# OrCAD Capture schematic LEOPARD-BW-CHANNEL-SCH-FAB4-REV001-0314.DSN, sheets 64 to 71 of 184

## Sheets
64 125_INTEL I210: size A2; title: INTEL I210
65 119_MB LED: size A3; title: MB LED
66 118_FAN - PWM: size A3; title: FAN -PWM
67 116_RESERVED PAGE: title: RESERVED PAGE
68 115_PECI: size A3; title: PECI
69 114_DEBUG PORT: size A3; title: DEBUG PORT
70 113_COM PORT: size A3; title: COM PORT
71 112_AST1250 ID SETTING: size A3; title: AST1250 ID SETTING

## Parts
sheet 112_AST1250 ID SETTING
R362  10KR2F-2-GP  [R402H16]
R366  10KR2F-2-GP  [R402H16]
R370  10KR2F-2-GP  [R402H16]
R378  10KR2F-2-GP  [R402H16]
R463  10KR2F-2-GP  [R402H16]
R465  10KR2F-2-GP  [R402H16]
R467  10KR2F-2-GP  [R402H16]
R468  10KR2F-2-GP  [R402H16]
R478  10KR2F-2-GP  [R402H16]
R484  10KR2F-2-GP  [R402H16]
R487  10KR2F-2-GP  [R402H16]
R494  10KR2F-2-GP  [R402H16]
R1132  10KR2F-2-GP  [R402H16]
R1134  10KR2F-2-GP  [R402H16]
R1136  10KR2F-2-GP  [R402H16]
R1138  10KR2F-2-GP  [R402H16]
R1140  10KR2F-2-GP  [R402H16]
R1141  10KR2F-2-GP  [R402H16]
R1157  10KR2F-2-GP  [R402H16]
R1158  10KR2F-2-GP  [R402H16]
R1159  10KR2F-2-GP  [R402H16]
R1160  10KR2F-2-GP  [R402H16]
R1161  10KR2F-2-GP  [R402H16]
R1162  10KR2F-2-GP  [R402H16]
R1163  10KR2F-2-GP  [R402H16]
R1164  10KR2F-2-GP  [R402H16]
R1165  10KR2F-2-GP  [R402H16]
R1166  10KR2F-2-GP  [R402H16]
R1167  10KR2F-2-GP  [R402H16]
R1168  10KR2F-2-GP  [R402H16]
R1169  10KR2F-2-GP  [R402H16]
R1170  10KR2F-2-GP  [R402H16]
sheet 113_COM PORT
C339  SCD1U16V2KX-3GP  [C402H22]
C688  SC180P50V2JN-1GP  [C402H22]
C689  SC180P50V2JN-1GP  [C402H22]
CN2  FCI-CON3-S1-GP  [68001-203HLF]
JP14  FCI-CON3-S1-GP  [68001-203HLF]
JP15  FCI-CON3-S1-GP  [68001-203HLF]
R262  0R2J-2-GP  [R402H16]
R263  0R2J-2-GP  [R402H16]
R372  1KR2F-3-GP  [R402H16]
R381  1KR2F-3-GP  [R402H16]
R1200  10KR2F-2-GP  [R402H16]
R1201  10KR2F-2-GP  [R402H16]
R1202  10KR2F-2-GP  [R402H16]
R1204  10KR2F-2-GP  [R402H16]
R1216  33R2F-3-GP  [R402H16]
R1218  33R2F-3-GP  [R402H16]
U46  SN74CB3Q3253PW-GP  [TSOIC16H48]
sheet 114_DEBUG PORT
C854  SCD1U16V2KX-3GP  [C402H22]
D4  BAT54C-12-GP  [SOT-23-9H44]
D27  1N4148WFL-GP  [SOD123AKH40]
D28  1N4148WFL-GP  [SOD123AKH40]
D29  1N4148WFL-GP  [SOD123AKH40]
DBG1  SMC-CONN14A-S5-GP  [ASP-165694-02]
JP5  FCI-CON3-S1-GP  [68001-203HLF]
Q4  LMBT3904LT1G-GP  [SOT23CBE2D4H44]
Q6  LMBT3904LT1G-GP  [SOT23CBE2D4H44]
Q7  2N7002-7F-GP  [SOT23DGS2D4H44]
Q23  2N7002-7F-GP  [SOT23DGS2D4H44]
R254  10KR2F-2-GP  [R402H16]
R271  0R2J-2-GP  [R402H16]
R280  0R2J-2-GP  [R402H16]
R374  15KR2F-GP  [R402H16]
R384  10KR2J-3-GP  [R402H16]
R385  10KR2J-3-GP  [R402H16]
R386  15KR2F-GP  [R402H16]
R387  10KR2J-3-GP  [R402H16]
R391  10KR2J-3-GP  [R402H16]
R407  0R2J-2-GP  [R402H16]
R409  1KR2J-1-GP  [R402H16]
R698  0R2J-2-GP  [R402H16]
R713  0R2J-2-GP  [R402H16]
R718  0R2J-2-GP  [R402H16]
R720  0R2J-2-GP  [R402H16]
R725  0R2J-2-GP  [R402H16]
sheet 115_PECI
R753  4K7R2F-GP  [R402H16]
R754  0R2J-2-GP  [R402H16]
R755  0R2J-2-GP  [R402H16]
R865  4K7R2F-GP  [R402H16]
sheet 118_FAN - PWM
C35  SCD1U50V3KX-GP  [C603H36]
C36  SCD1U50V3KX-GP  [C603H36]
C88  SCD1U16V2KX-3GP  [C402H22]
D12  MMSZ4701-V-GP  [SOD123AKH54]
D20  SDMK0340L-7-F-GP  [SOD323AKH42]
D21  SDMK0340L-7-F-GP  [SOD323AKH42]
D22  SDMK0340L-7-F-GP  [SOD323AKH42]
D23  SDMK0340L-7-F-GP  [SOD323AKH42]
D24  SDMK0340L-7-F-GP  [SOD323AKH42]
D25  SDMK0340L-7-F-GP  [SOD323AKH42]
F6  FUSE-15A65V-3-GP  [FUSE-6127H106]
FANCN1  LOTES-CON6-S1-GP  [YBA-WAF-016-K06]
FANCN2  LOTES-CON6-S1-GP  [YBA-WAF-016-K06]
R741  2K21R2F-GP  [R402H16]
R742  0R2J-2-GP  [R402H16]
R743  0R2J-2-GP  [R402H16]
R744  0R2J-2-GP  [R402H16]
R745  0R2J-2-GP  [R402H16]
R746  2K21R2F-GP  [R402H16]
R747  0R2J-2-GP  [R402H16]
R748  0R2J-2-GP  [R402H16]
R895  4K7R2F-GP  [R402H16]
R903  4K7R2F-GP  [R402H16]
U168  SOLVC2G07DBVR-GP  [SOT-6H58]
sheet 119_MB LED
BPLED1  LED-Y-70-GP  [LED3020AK-U2H44]
C1299  SCD1U16V2KX-3GP  [C402H22]
HDLED1  LED-G-147-GP  [LED3020AK-U2H44]
PWLED1  LED-B-77-GP-U3  [LED3020AK-U2H44]
Q20  2N7002-7F-GP  [SOT23DGS2D4H44]
R799  100R3F-1-GP  [R603H22]
R806  100R3F-1-GP  [R603H22]
R807  100R3F-1-GP  [R603H22]
R1155  100R3F-1-GP  [R603H22]
R1156  200R2F-L-GP  [R402H16]
R1868  0R2J-2-GP  [R402H16]
R1881  10KR2J-3-GP  [R402H16]
U42  74LVC1G86GW-GP  [SC70-5H44]
U48  NTJD4001NT1G-1-GP  [SOT-363H44]
ULED1  LED-G-107-GP-U  [LED11516AKH28]
ULED2  LED-G-107-GP-U  [LED11516AKH28]
sheet 125_INTEL I210
C317  SCD1U16V2KX-3GP  [C402H22]
C318  SCD1U16V2KX-3GP  [C402H22]
C319  SCD039U16V2KX-GP  [C402H22]
C323  SCD1U16V2KX-3GP  [C402H22]
C7280  SC12P50V2JN-3GP  [C402H24]
C7282  SC12P50V2JN-3GP  [C402H24]
LAN1  WGI210AT-2-GP  [QFN64G9-G3D6H40]  (sections A,B,C,D)
R343  0R3J-0-U-GP  [R603H22]
R344  0R3J-0-U-GP  [R603H22]
R383  0R3J-0-U-GP  [R603H22]
R894  10KR2F-2-GP  [R402H16]
R902  10KR2F-2-GP  [R402H16]
R904  10KR2F-2-GP  [R402H16]
R906  10KR2F-2-GP  [R402H16]
R907  100KR2J-1-GP  [R402H16]
R938  10KR2F-2-GP  [R402H16]
R941  10KR2F-2-GP  [R402H16]
R942  10KR2F-2-GP  [R402H16]
R949  3K3R2F-2-GP  [R402H16]
R950  3K3R2F-2-GP  [R402H16]
R951  3K3R2F-2-GP  [R402H16]
R953  3K3R2F-2-GP  [R402H16]
R978  3K3R2F-2-GP  [R402H16]
R982  3K3R2F-2-GP  [R402H16]
R1002  3K3R2F-2-GP  [R402H16]
R1004  3K3R2F-2-GP  [R402H16]
R1005  33K2R2F-GP  [R402H16]
R1008  33K2R2F-GP  [R402H16]
R1009  3K3R2F-2-GP  [R402H16]
R1010  33R2F-3-GP  [R402H16]
R1011  33R2F-3-GP  [R402H16]
R1012  33R2F-3-GP  [R402H16]
R1013  33R2F-3-GP  [R402H16]
R1014  33R2F-3-GP  [R402H16]
R1015  0R2J-2-GP  [R402H16]
R1232  10KR2F-2-GP  [R402H16]
R2126  0R2J-2-GP  [R402H16]
R2127  0R2J-2-GP  [R402H16]
R2129  4K99R2F-L-GP  [R402H16]
R2134  33R2F-3-GP  [R402H16]
R2157  10KR2F-2-GP  [R402H16]
R2158  10KR2F-2-GP  [R402H16]
R2159  10KR2F-2-GP  [R402H16]
R2165  0R2J-2-GP  [R402H16]
R2166  0R2J-2-GP  [R402H16]
TP471  TPAD28  [TPAD28]
TP472  TPAD28  [TPAD28]
TP474  TPAD28  [TPAD28]
TP475  TPAD28  [TPAD28]
TP476  TPAD28  [TPAD28]
TP477  TPAD28  [TPAD28]
TP478  TPAD28  [TPAD28]
TP479  TPAD28  [TPAD28]
TP480  TPAD28  [TPAD28]
U40  W25Q80DVSSIG-GP  [SOIC8-1H86]
X6  XTAL-25MHZ-96GP  [SMD49-4H56]

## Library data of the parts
R362 R378 R465 R478 R484 R487 R1134 R1161 = 10KR2F-2-GP: CHIP RES 10K F 1/16W 0402; Category: 240VA; GREENDFACTOR: R2_SA;R_SA;HF_SA;G_SA;; Level: SMD; Part Number: 64.10025.6DL; Part Type: SMD-RG; SPEC: http://wpqssvr.wistron.com.tw:7001/wpqs/servlet/COM.qpart.Attachment?PartNumber=64.10025.6DL
R366 R370 R463 R467 R468 R494 R1138 R1164 = 10KR2F-2-GP: CHIP RES 10K F 1/16W 0402; Category: 240VA; GREENDFACTOR: R2_SA;R_SA;HF_SA;G_SA;; Level: SMD; POP?: NOPOP; Part Number: 64.10025.6DL; Part Type: SMD-RG; SPEC: http://wpqssvr.wistron.com.tw:7001/wpqs/servlet/COM.qpart.Attachment?PartNumber=64.10025.6DL
R1132 R1136 R1162 R1163 = 10KR2F-2-GP: CHIP RES 10K F 1/16W 0402; Category: 240VA; GREENDFACTOR: R2_SA;R_SA;HF_SA;G_SA;; Level: SMD; POP?: NOPOP; Part Number: 64.10025.6DL; Part Type: SMD-RG; SPEC: http://wpqssvr.wistron.com.tw:7001/wpqs/servlet/COM.qpart.Attachment?PartNumber=64.10025.6DL; Status: POP
R1140 R1157 R1159 R1165 R1167 R1169 = 10KR2F-2-GP: CHIP RES 10K F 1/16W 0402; Category: 240VA; GREENDFACTOR: R2_SA;R_SA;HF_SA;G_SA;; Level: SMD; Part Number: 64.10025.6DL; Part Type: SMD-RG; SPEC: http://wpqssvr.wistron.com.tw:7001/wpqs/servlet/COM.qpart.Attachment?PartNumber=64.10025.6DL; Status: NOPOP
R1141 R1168 R1200-R1202 R1204 = 10KR2F-2-GP: CHIP RES 10K F 1/16W 0402; Category: 240VA; GREENDFACTOR: R2_SA;R_SA;HF_SA;G_SA;; Level: SMD; Part Number: 64.10025.6DL; Part Type: SMD-RG; SPEC: http://wpqssvr.wistron.com.tw:7001/wpqs/servlet/COM.qpart.Attachment?PartNumber=64.10025.6DL; Status: POP
R1158 R1160 R1166 R1170 = 10KR2F-2-GP: CHIP RES 10K F 1/16W 0402; Category: 240VA; GREENDFACTOR: R2_SA;R_SA;HF_SA;G_SA;; Level: SMD; POP?: NOPOP; Part Number: 64.10025.6DL; Part Type: SMD-RG; SPEC: http://wpqssvr.wistron.com.tw:7001/wpqs/servlet/COM.qpart.Attachment?PartNumber=64.10025.6DL; Status: NOPOP
C339 = SCD1U16V2KX-3GP: CHIP CAP C 0.1U 16V K0402 X7R; CATEGORIES: CAP_1.xV; GREENDFACTOR: R2_SA;HF_SA;G_SA;; MAIN_SOURCE: M; Part Number: 78.10421.2FL; Part Type: SMD-BCG; SPEC: http://wpqssvr.wistron.com.tw:7001/wpqs/servlet/COM.qpart.Attachment?PartNumber=78.10421.2FL
C688 C689 = SC180P50V2JN-1GP: CHIP CAP C 180P 50V J0402 NPO; GREENDFACTOR: R2_SA;HF_SA;G_SA;; Package Type: SMD-BCG; Part Number: 78.18134.1FL; SPEC: http://wpqssvr.wistron.com.tw:7001/wpqs/servlet/COM.qpart.Attachment?PartNumber=78.18134.1FL
CN2 JP14 JP15 = FCI-CON3-S1-GP: HEAD ML 1R3P ST 68001-203HLF; Category: PCH; GREENDFACTOR: R_SA;; Green Factor: R_SA;; Part Number: 21.61084.103; Part Type: CONN-G4; ROOM: IMMv2; S/D: DIP; SPEC: http://wpqssvr.wistron.com.tw:7001/wpqs/servlet/COM.qpart.Attachment?PartNumber=21.61084.103; Vender: FCI
R262 R263 = 0R2J-2-GP: CHIP RES 0 J 1/16W 0402; Category: LOM - i350; DESCRIPTIO: CHIP RES 0 J 1/16W 0402; GREENDFACTOR: R2_SA;HF_SA;G_SA;; Package Type: SMD-RG; Part Number: 63.R0034.1DL; Part Type: SMD-RG; SPEC: http://wpqssvr.wistron.com.tw:7001/wpqs/servlet/COM.qpart.Attachment?PartNumber=63.R0034.1DL; VENDORPARTNUMBER: RM04JTN0/RTT02000JTH/RR0510X-000-XN/RC0402JR-070RL/WR04X000 PTL
R372 R381 = 1KR2F-3-GP: CHIP RES 1K F 1/16W 0402; GREENDFACTOR: R2_SA;HF_SA;G_SA;; Package Type: SMD-RG; Part Number: 64.10015.6DL; SPEC: http://wpqssvr.wistron.com.tw:7001/wpqs/servlet/COM.qpart.Attachment?PartNumber=64.10015.6DL
R1216 R1218 = 33R2F-3-GP: CHIP RES 33 F 1/16W 0402(ROHS); Category: PILOT3; GREENDFACTOR: R2_SA;HF_SA;G_SA;; Package Type: SMD-RG; Part Number: 64.33R05.6DL; Quotation: 12_14; Type: SMD
U46 = SN74CB3Q3253PW-GP: IC BUS SN74CB3Q3253PW TSSOP16P; GREENDFACTOR: R2_SA;; Part Number: 73.03253.A0B; Part Type: DISCRET-G4; SPEC: http://wpqssvr.wistron.com.tw:7001/wpqs/servlet/COM.qpart.Attachment?PartNumber=73.03253.A0B
C854 = SCD1U16V2KX-3GP: CHIP CAP C 0.1U 16V K0402 X7R; Belong: POP; CATEGORIES: CAP_1.xV; Category: USB SW / Debug; GREENDFACTOR: R2_SA;HF_SA;G_SA;; MAIN_SOURCE: M; Part Number: 78.10421.2FL; Part Type: SMD-BCG; SPEC: http://wpqssvr.wistron.com.tw:7001/wpqs/servlet/COM.qpart.Attachment?PartNumber=78.10421.2FL
D4 = BAT54C-12-GP: IC DIODE S.B BAT54C SOT-23; GREENDFACTOR: R2_SA;HF_SA;G_SA;; Package Type: DISCRET-G9; Part Number: 75.00054.A7D; SPEC: http://wpqssvr.wistron.com.tw:7001/wpqs/servlet/COM.qpart.Attachment?PartNumber=75.00054.A7D
D27-D29 = 1N4148WFL-GP: DIODE SW 1N4148WFL SOD-123; Belong: POP; Category: I/O CONN; GREENDFACTOR: R_SA;HF_SA;; Part Number: 83.04148.F1H; Part Type: DISCRET-G5; SPEC: http://wpqssvr.wistron.com.tw:7001/wpqs/servlet/COM.qpart.Attachment?PartNumber=83.04148.F1H
DBG1 = SMC-CONN14A-S5-GP: CONN CTR 14P ASP-165694-02; GREENDFACTOR: R2_C;HF_C;; Part Number: 020.80491.0014; Part Type: CONN-G4; SPEC: http://wpqssvr.wistron.com.tw:7001/wpqs/servlet/COM.qpart.Attachment?PartNumber=020.80491.0014
JP5 = FCI-CON3-S1-GP: HEAD ML 1R3P ST 68001-203HLF; GREENDFACTOR: R2_SA;; Part Number: 21.61084.103; Part Type: CONN-G4; SPEC: http://wpqssvr.wistron.com.tw:7001/wpqs/servlet/COM.qpart.Attachment?PartNumber=21.61084.103
Q4 Q6 = LMBT3904LT1G-GP: XTOR LMBT3904LT1G NPN SOT-23; GREENDFACTOR: R2_SA;HF_SA;G_SA;; Part Number: 84.T3904.H11; Part Type: DISCRET-G6; SPEC: http://wpqssvr.wistron.com.tw:7001/wpqs/servlet/COM.qpart.Attachment?PartNumber=84.T3904.H11
Q7 Q20 Q23 = 2N7002-7F-GP: FET MOS 2N7002-7-F NC SOT-23; GREENDFACTOR: R2_SA;HF_SA;G_SA;; Part Number: 84.27002.N31; Part Type: DISCRET-G; SPEC: http://wpqssvr.wistron.com.tw:7001/wpqs/servlet/COM.qpart.Attachment?PartNumber=84.27002.N31
R254 = 10KR2F-2-GP: CHIP RES 10K F 1/16W 0402; Category: PCH; DESCRIPTIO: CHIP RES 10K F 1/16W 0402; GREENDFACTOR: R2_SA;HF_SA;G_SA;; Package Type: SMD-RG; Part Number: 64.10025.6DL; Part Type: SMD-RG; SPEC: http://wpqssvr.wistron.com.tw:7001/wpqs/servlet/COM.qpart.Attachment?PartNumber=64.10025.6DL; VENDORPARTNUMBER: RM04FTN1002 / RTT021002FTH / RR0510S-103-FN / RC0402FR-0710KL/WR04X1002FTL
R271 R280 R407 R698 R713 R718 R720 R725 R742-R745 R747 R748 R755 R1868 = 0R2J-2-GP: CHIP RES 0 J 1/16W 0402; Category: BMC; DESCRIPTIO: CHIP RES 0 J 1/16W 0402; GREENDFACTOR: R2_SA;HF_SA;G_SA;; Package Type: SMD-RG; Part Number: 63.R0034.1DL; Part Type: SMD-RG; SPEC: http://wpqssvr.wistron.com.tw:7001/wpqs/servlet/COM.qpart.Attachment?PartNumber=63.R0034.1DL; VENDORPARTNUMBER: RM04JTN0/RTT02000JTH/RR0510X-000-XN/RC0402JR-070RL/WR04X000 PTL
R374 R386 = 15KR2F-GP: CHIP RES 15K F 1/16W 0402; GREENDFACTOR: R2_SA;HF_SA;G_SA;; Part Number: 64.15025.6DL; Part Type: RCL_GP; SPEC: http://wpqssvr.wistron.com.tw:7001/wpqs/servlet/COM.qpart.Attachment?PartNumber=64.15025.6DL
R384 R385 R387 R391 R1881 = 10KR2J-3-GP: CHIP RES 10K J 1/16W 0402; Category: PWRI/O CONN; GREENDFACTOR: R2_SA;HF_SA;G_SA;; Module: Internal Connector; Package Type: SMD-RG; Part Number: 63.10334.1DL; SPEC: http://wpqssvr.wistron.com.tw:7001/wpqs/servlet/COM.qpart.Attachment?PartNumber=63.10334.1DL
R409 = 1KR2J-1-GP: CHIP RES 1K J 1/16W 0402; GREENDFACTOR: R2_SA;HF_SA;G_SA;; Part Number: 63.10234.1DL; Part Type: SMD-RG; SPEC: http://wpqssvr.wistron.com.tw:7001/wpqs/servlet/COM.qpart.Attachment?PartNumber=63.10234.1DL
R753 = 4K7R2F-GP: CHIP RES 4.7K F 1/16W 0402; Category: BMC; DESCRIPTIO: CHIP RES 4.7K F 1/16W 0402; GREENDFACTOR: R2_SA;HF_SA;G_SA;; POP?: NOPOP; Package Type: RCL_GP; Part Number: 64.47015.6DL; Part Type: RCL_GP; SPEC: http://wpqssvr.wistron.com.tw:7001/wpqs/servlet/COM.qpart.Attachment?PartNumber=64.47015.6DL; VENDORPARTNUMBER: RM04FTN4701/RTT024701FTH/RR0510S-472-FN/RC0402FR-074K7L/WR04X4701FTL
R754 = 0R2J-2-GP: CHIP RES 0 J 1/16W 0402; Category: BMC; DESCRIPTIO: CHIP RES 0 J 1/16W 0402; GREENDFACTOR: R2_SA;HF_SA;G_SA;; POP?: NOPOP; Package Type: SMD-RG; Part Number: 63.R0034.1DL; Part Type: SMD-RG; SPEC: http://wpqssvr.wistron.com.tw:7001/wpqs/servlet/COM.qpart.Attachment?PartNumber=63.R0034.1DL; VENDORPARTNUMBER: RM04JTN0/RTT02000JTH/RR0510X-000-XN/RC0402JR-070RL/WR04X000 PTL
R865 = 4K7R2F-GP: CHIP RES 4.7K F 1/16W 0402; Category: BMC; DESCRIPTIO: CHIP RES 4.7K F 1/16W 0402; GREENDFACTOR: R2_SA;HF_SA;G_SA;; Package Type: RCL_GP; Part Number: 64.47015.6DL; Part Type: RCL_GP; SPEC: http://wpqssvr.wistron.com.tw:7001/wpqs/servlet/COM.qpart.Attachment?PartNumber=64.47015.6DL; VENDORPARTNUMBER: RM04FTN4701/RTT024701FTH/RR0510S-472-FN/RC0402FR-074K7L/WR04X4701FTL
C35 C36 = SCD1U50V3KX-GP: CHIP CAP C 0.1U 50V K0603 X7R; CATEGORIES: CAP_1.xV; GREENDFACTOR: R2_SA;R_SA;HF_SA;G_SA;; MAIN_SOURCE: M; Package Type: RCL_GP; Part Number: 78.10424.2BL; SPEC: http://wpqssvr.wistron.com.tw:7001/wpqs/servlet/COM.qpart.Attachment?PartNumber=78.10424.2BL
C88 = SCD1U16V2KX-3GP: CHIP CAP C 0.1U 16V K0402 X7R; Category: CLK GEN; GREENDFACTOR: R_SA;HF_SA;G_SA;; Part Number: 78.10421.2FL; Quotation: 13_8; Type: SMD
D12 = MMSZ4701-V-GP: DIODE ZENER MMSZ4701-V SOD123; GREENDFACTOR: R_C;; POP?: NOPOP; Package Type: DISCRET-G; Part Number: 83.14R03.03H; SPEC: http://wpqssvr.wistron.com.tw:7001/wpqs/servlet/COM.qpart.Attachment?PartNumber=83.14R03.03H
D20-D23 = SDMK0340L-7-F-GP: DIODE SDMK0340L-7-F SOD-323; GREENDFACTOR: R2_SA;HF_SA;; Part Number: 83.R3004.A8F; Part Type: DISCRET-G; SPEC: http://wpqssvr.wistron.com.tw:7001/wpqs/servlet/COM.qpart.Attachment?PartNumber=83.R3004.A8F
D24 D25 = SDMK0340L-7-F-GP: DIODE SDMK0340L-7-F SOD-323; GREENDFACTOR: R2_SA;HF_SA;G_SA;; POP?: NOPOP; Part Number: 83.R3004.A8F; Part Type: DISCRET-G; SPEC: http://wpqssvr.wistron.com.tw:7001/wpqs/servlet/COM.qpart.Attachment?PartNumber=83.R3004.A8F
F6 = FUSE-15A65V-3-GP: CHIP FUSE 15A 65V R451015; GREENDFACTOR: R_SA;; Part Number: 69.41502.011; Part Type: DISCRET-G6; SPEC: http://wpqssvr.wistron.com.tw:7001/wpqs/servlet/COM.qpart.Attachment?PartNumber=69.41502.011
FANCN1 FANCN2 = LOTES-CON6-S1-GP: HEAD ML 1R6P ST YBA-WAF-016-K06; GREENDFACTOR: R2_C;; Part Number: 21.61901.106; Part Type: CONN-G5; SPEC: http://wpqssvr.wistron.com.tw:7001/wpqs/servlet/COM.qpart.Attachment?PartNumber=21.61901.106
R741 R746 = 2K21R2F-GP: CHIP RES 2.21K F 1/16W 0402; Category: HOTPLUG_CONTROL; GREENDFACTOR: R2_SA;HF_SA;G_SA;; POP?: NOPOP; Package Type: RCL_GP; Part Number: 64.22115.6DL; Part Type: RCL_GP; SPEC: http://wpqssvr.wistron.com.tw:7001/wpqs/servlet/COM.qpart.Attachment?PartNumber=64.22115.6DL
R895 R903 = 4K7R2F-GP: CHIP RES 4.7K F 1/16W 0402; Category: internal conn; DESCRIPTIO: CHIP RES 4.7K F 1/16W 0402; GREENDFACTOR: R2_SA;HF_SA;G_SA;; POP?: NOPOP; Package Type: RCL_GP; Part Number: 64.47015.6DL; Part Type: RCL_GP; SPEC: http://wpqssvr.wistron.com.tw:7001/wpqs/servlet/COM.qpart.Attachment?PartNumber=64.47015.6DL; VENDORPARTNUMBER: RM04FTN4701/RTT024701FTH/RR0510S-472-FN/RC0402FR-074K7L/WR04X4701FTL
U168 = SOLVC2G07DBVR-GP: IC BUF/DRV SN74LVC2G07DBVR SOT23-6; GREENDFACTOR: R2_SA;HF_SA;; Part Number: 73.2G07D.020; Part Type: TTL-G6; SPEC: http://wpqssvr.wistron.com.tw:7001/wpqs/servlet/COM.qpart.Attachment?PartNumber=73.2G07D.020
BPLED1 = LED-Y-70-GP: LED YEL 12-21UYC/S530-A3/TR8; Category: LED_WOL; GREENDFACTOR: R_SA;; POP?: POP; Part Number: 83.01221.Q70; Part Type: DISCRET-G5; SPEC: http://wpqssvr.wistron.com.tw:7001/wpqs/servlet/COM.qpart.Attachment?PartNumber=83.01221.Q70
C1299 = SCD1U16V2KX-3GP: CHIP CAP C 0.1U 16V K0402 X7R; Belong: POP; CATEGORIES: CAP_1.xV; Category: UID LED; GREENDFACTOR: R2_SA;HF_SA;G_SA;; MAIN_SOURCE: M; Part Number: 78.10421.2FL; Part Type: SMD-BCG; SPEC: http://wpqssvr.wistron.com.tw:7001/wpqs/servlet/COM.qpart.Attachment?PartNumber=78.10421.2FL
HDLED1 = LED-G-147-GP: LED G 12-21SYGC/S530-E4/TR8; Category: LED_WOL; GREENDFACTOR: R2_SA;; POP?: POP; Part Number: 83.01221.N70; Part Type: DISCRET-G2; SPEC: http://wpqssvr.wistron.com.tw:7001/wpqs/servlet/COM.qpart.Attachment?PartNumber=83.01221.N70
PWLED1 = LED-B-77-GP-U3: LED BLUE 12-21/BHC-YLMRY-2C; Category: UID LED; GREENDFACTOR: R2_SA;HF_SA;; POP?: POP; Package Type: DISCRET-G6; Part Number: 83.01221.I70; SPEC: http://wpqssvr.wistron.com.tw:7001/wpqs/servlet/COM.qpart.Attachment?PartNumber=83.01221.I70
R799 R806 R807 R1155 = 100R3F-1-GP: CHIP RES 100 F 1/10W 0603(ROHS; Category: LED_WOL; GREENDFACTOR: R2_SA;HF_SA;G_SA;; Package Type: SMD-RG6; Part Number: 64.10005.55L; SPEC: http://wpqssvr.wistron.com.tw:7001/wpqs/servlet/COM.qpart.Attachment?PartNumber=64.10005.55L
R1156 = 200R2F-L-GP: CHIP RES 200 F 1/16W 0402; Belong: POP; Category: UID LED; GREENDFACTOR: R2_SA;HF_SA;G_SA;; Part Number: 64.20005.6DL; Part Type: SMD-RG; SPEC: http://wpqssvr.wistron.com.tw:7001/wpqs/servlet/COM.qpart.Attachment?PartNumber=64.20005.6DL
U42 = 74LVC1G86GW-GP: IC CMOS 74LVC1G86GW SC-88A; GREENDFACTOR: R2_SA;HF_SA;; Part Number: 73.01G86.AHH; Part Type: DISCRET-G; SPEC: http://wpqssvr.wistron.com.tw:7001/wpqs/servlet/COM.qpart.Attachment?PartNumber=73.01G86.AHH
U48 = NTJD4001NT1G-1-GP: IC MOSFET NTJD4001NT1G NC SOT-363 6P; GREENDFACTOR: R2_SA;; Part Number: 75.04001.07C; Part Type: DISCRET-G5; SPEC: http://wpqssvr.wistron.com.tw:7001/wpqs/servlet/COM.qpart.Attachment?PartNumber=75.04001.07C
ULED1 ULED2 = LED-G-107-GP-U: LED GREEN LTST-S270KGKT SMD; GREENDFACTOR: R2_SA;HF_SA;G_SA;; Part Number: 83.00270.B70; Part Type: DISCRET-G; SPEC: http://wpqssvr.wistron.com.tw:7001/wpqs/servlet/COM.qpart.Attachment?PartNumber=83.00270.B70
C317 C318 C323 = SCD1U16V2KX-3GP: CHIP CAP C 0.1U 16V K0402 X7R; Category: CLK GEN; GREENDFACTOR: R_SA;HF_SA;G_SA;; POP?: NOPOP; Part Number: 78.10421.2FL; Quotation: 13_8; Type: SMD
C319 = SCD039U16V2KX-GP: CHIP CAP C 0.039U 16V K0402 X7; GREENDFACTOR: R2_SA;HF_SA;G_SA;; POP?: NOPOP; Package Type: SMD-BCG3; Part Number: 78.39321.2FL; SPEC: http://wpqssvr.wistron.com.tw:7001/wpqs/servlet/COM.qpart.Attachment?PartNumber=78.39321.2FL
C7280 C7282 = SC12P50V2JN-3GP: CHIP CAP C 12P 50V J0402 NPO; CATEGORIES: CAP_Small; Category: Clock; GREENDFACTOR: R2_SA;HF_SA;G_SA;; MAIN_SOURCE: M; POP?: NOPOP; Package Type: SMD-BCG; Part Number: 78.12034.1FL; Part Type: SMD-BCG; SPEC: http://wpqssvr.wistron.com.tw:7001/wpqs/servlet/COM.qpart.Attachment?PartNumber=78.12034.1FL; VENDORPARTNUMBER: 04025A120JAT2A/GRM1555C1H120JZ01D/223886915129/UMK105CH120JW-F/C1005C0G1H120J/C1005NP0120JGT/GRM1555C1H120JA01D/0402N120J500
LAN1 = WGI210AT-2-GP: IC WGI210AT SLJXR MM#925132 A2 QFN 64P; GREENDFACTOR: R2_SA;; POP?: NOPOP; Part Number: 071.210AT.0003; Part Type: ASIC2-GB1; SPEC: http://wpqssvr.wistron.com.tw:7001/wpqs/servlet/COM.qpart.Attachment?PartNumber=071.210AT.0003
R343 R344 R383 = 0R3J-0-U-GP: CHIP RES 0 J 1/10W 0603; GREENDFACTOR: R2_SA;HF_SA;G_SA;; POP?: NOPOP; Package Type: RCL_GP; Part Number: 63.00000.00L; SPEC: http://wpqssvr.wistron.com.tw:7001/wpqs/servlet/COM.qpart.Attachment?PartNumber=63.00000.00L
R894 R902 R904 R906 R941 R942 R2157 R2158 = 10KR2J-3-GP: CHIP RES 10K F 1/16W 0402; Category: PCH; DESCRIPTIO: CHIP RES 10K J 1/16W 0402; GREENDFACTOR: R2_SA;HF_SA;G_SA;; POP?: NOPOP; Package Type: SMD-RG; Part Number: 64.10025.6DL; Part Type: SMD-RG; SPEC: http://wpqssvr.wistron.com.tw:7001/wpqs/servlet/COM.qpart.Attachment?PartNumber=64.10025.6DL; Type: SMD; VENDORPARTNUMBER: RM04FTN1002 / RTT021002FTH / RR0510S-103-FN / RC0402FR-0710KL/WR04X1002FTL; Vendor PN: RR0510S-103-JN/RTT02103JTH/RM04JTN103/WR04X103JTL/RC0402JR-0710KL
R907 = 100KR2J-1-GP: CHIP RES 100K J 1/16W 0402; GREENDFACTOR: R2_SA;HF_SA;G_SA;; POP?: NOPOP; Part Number: 63.10434.1DL; Part Type: SMD-RG; SPEC: http://wpqssvr.wistron.com.tw:7001/wpqs/servlet/COM.qpart.Attachment?PartNumber=63.10434.1DL
R938 R1232 R2159 = 10KR2J-3-GP: CHIP RES 10K F 1/16W 0402; Category: PCH; DESCRIPTIO: CHIP RES 10K J 1/16W 0402; GREENDFACTOR: R2_SA;HF_SA;G_SA;; Package Type: SMD-RG; Part Number: 64.10025.6DL; Part Type: SMD-RG; SPEC: http://wpqssvr.wistron.com.tw:7001/wpqs/servlet/COM.qpart.Attachment?PartNumber=64.10025.6DL; Type: SMD; VENDORPARTNUMBER: RM04FTN1002 / RTT021002FTH / RR0510S-103-FN / RC0402FR-0710KL/WR04X1002FTL; Vendor PN: RR0510S-103-JN/RTT02103JTH/RM04JTN103/WR04X103JTL/RC0402JR-0710KL
R949-R951 R953 R978 = 3K3R2J-3-GP: CHIP RES 3.3K F 1/16W 0402; Category: LOM - i350; DESCRIPTIO: CHIP RES 3.3K J 1/16W 0402; GREENDFACTOR: R2_SA;HF_SA;G_SA;; POP?: NOPOP; Package Type: SMD-RG; Part Number: 64.33015.6DL; Part Type: SMD-RG; SPEC: http://wpqssvr.wistron.com.tw:7001/wpqs/servlet/COM.qpart.Attachment?PartNumber=64.33015.6DL; VENDORPARTNUMBER: RM04FTN3301/RTT023301FTH/RR0510S-332-FN/RC0402FR-073K3L; Vendor PN: RM04JTN332/RTT02332JTH/RR-0510S-332-JN/RC0402JR-073K3L/WR04X332JTL
R982 R1002 R1004 R1009 = 3K3R2F-2-GP: CHIP RES 3.3K F 1/16W 0402; GREENDFACTOR: R2_SA;HF_SA;G_SA;; POP?: NOPOP; Package Type: SMD-RG; Part Number: 64.33015.6DL; SPEC: http://wpqssvr.wistron.com.tw:7001/wpqs/servlet/COM.qpart.Attachment?PartNumber=64.33015.6DL
R1005 R1008 = 33K2R2F-GP: CHIP RES 33.2K F 1/16W 0402; GREENDFACTOR: R2_SA;HF_SA;G_SA;; POP?: NOPOP; Package Type: RCL_GP; Part Number: 64.33225.6DL; SPEC: http://wpqssvr.wistron.com.tw:7001/wpqs/servlet/COM.qpart.Attachment?PartNumber=64.33225.6DL
R1010-R1014 R2134 = 33R2F-3-GP: CHIP RES 33 F 1/16W 0402(ROHS); GREENDFACTOR: R2_SA;HF_SA;G_SA;; POP?: NOPOP; Package Type: SMD-RG; Part Number: 64.33R05.6DL; SPEC: http://wpqssvr.wistron.com.tw:7001/wpqs/servlet/COM.qpart.Attachment?PartNumber=64.33R05.6DL
R1015 R2126 R2127 R2165 R2166 = 0R2J-2-GP: CHIP RES 0 J 1/16W 0402; Category: LOM - i350; DESCRIPTIO: CHIP RES 0 J 1/16W 0402; GREENDFACTOR: R2_SA;HF_SA;G_SA;; POP?: NOPOP; Package Type: SMD-RG; Part Number: 63.R0034.1DL; Part Type: SMD-RG; SPEC: http://wpqssvr.wistron.com.tw:7001/wpqs/servlet/COM.qpart.Attachment?PartNumber=63.R0034.1DL; VENDORPARTNUMBER: RM04JTN0/RTT02000JTH/RR0510X-000-XN/RC0402JR-070RL/WR04X000 PTL; Vendor PN: RM04JTN0/RTT02000JTH/RR0510X-000-XN/RC0402JR-070RL/WR04X000 PTL
R2129 = 4K99R2F-L-GP: CHIP RES 4.99K F 1/16W 0402; GREENDFACTOR: R2_SA;HF_SA;G_SA;; POP?: NOPOP; Package Type: SMD-RG; Part Number: 64.49915.6DL; SPEC: http://wpqssvr.wistron.com.tw:7001/wpqs/servlet/COM.qpart.Attachment?PartNumber=64.49915.6DL
TP471 TP472 TP474-TP480 = TP-2: TEST PAD28; Category: LOM - i350; GREENDFACTOR: Regular;; Package Type: DISCRETE; Part Number: ZZ.PAD28.XXX; Part Type: DISCRETE; SPEC: http://wpqssvr.wistron.com.tw:7001/wpqs/servlet/COM.qpart.Attachment?PartNumber=ZZ.PAD28.XXX; Type: SMD
U40 = W25Q80DVSSIG-GP: IC FEROM W25Q80DVSSIG SOIC 8P 1M-BYTE; GREENDFACTOR: R2_C;; POP?: NOPOP; Part Number: 072.25Q80.0001; Part Type: MEMORY-G4; SPEC: http://wpqssvr.wistron.com.tw:7001/wpqs/servlet/COM.qpart.Attachment?PartNumber=072.25Q80.0001
X6 = XTAL-25MHZ-96GP: XTAL 25MHZ 12P X5H025000FC1H-H; GREENDFACTOR: R2_SA;HF_SA;G_SA;; POP?: NOPOP; Package Type: DISCRET-G1; Part Number: 82.30020.791; SPEC: http://wpqssvr.wistron.com.tw:7001/wpqs/servlet/COM.qpart.Attachment?PartNumber=82.30020.791

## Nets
GND: C35.1 C36.1 C88.2 C323.1 C339.2 C688.2 C689.2 C854.2 C1299.2 C7280.1 C7282.1 CN2.3 D12.A(ANODE) DBG1.13 FANCN1.1 FANCN2.1 LAN1.65(GND) Q6.E Q7.S Q20.S Q23.S R362.2 R378.2 R384.2 R465.2 R467.2 R487.2 R494.2 R1008.2 R1009.2 R1132.2 R1136.2 R1141.2 R1157.2 R1160.2 R1162.2 R1163.2 R1166.2 R1168.2 R1169.2 R1200.2 R1201.2 R1202.2 R1204.2 R2129.1 R2157.1 R2158.1 R2159.1 U40.4(GND) U42.3(GND) U46.8(GND) U48.1(S1) U48.4(S2) U168.2(GND) ; also on sheet 1 2 3 4 5 6 7 8 9 10 11 12 13 14 15 16 17 18 19 20 21 22 23 24 25 26 27 28 29 30 31 32 33 34 35 36 37 38 39 44 46 47 49 50 51 52 53 54 55 56 57 58 59 60 61 62 63 73 74 75 76 78 79 80 81 82 83 84 86 87 88 89 90 91 92 93 94 95 96 97 98 99 100 101 102 103 104 105 106 107 108 109 110 111 112 113 114 115 116 117 118 119 128 129 138 139 159 160 161 166 168 169 170 171 172 173 174 175 176 177 180 181 182 183 184
P0V9_I210: LAN1.11(VDD0P9) LAN1.32(VDD0P9) LAN1.38(VDD0P9_OUT) LAN1.42(VDD0P9) LAN1.59(VDD0P9) ; also on sheet 62
P1V5_I210: LAN1.39(VDD1P5_OUT) LAN1.47(VDD1P5) R343.1 R344.1 ; also on sheet 62
P3V3: R799.1 R806.1 R807.1 R1155.1 ; also on sheet 1 3 8 45 46 48 49 52 54 58 74 76 78 83 84 87 90 91 94 95 96 100 101 102 161 166 168 173 174 177 180 181 182 183
P3V3_STBY: C88.1 C323.2 C339.1 C1299.1 LAN1.10(VDD3P3) LAN1.27(VDD3P3) LAN1.41(VDD3P3) LAN1.64(VDD3P3) R254.2 R366.2 R370.2 R372.1 R381.1 R383.1 R385.1 R387.1 R391.1 R409.1 R463.2 R468.2 R478.2 R484.2 R894.1 R895.1 R902.1 R903.1 R904.1 R906.1 R907.2 R938.1 R941.1 R942.1 R949.2 R950.2 R951.2 R953.2 R978.2 R982.1 R1002.1 R1004.1 R1005.1 R1134.2 R1138.2 R1140.2 R1158.2 R1159.2 R1161.2 R1164.2 R1165.2 R1167.2 R1170.2 R1232.1 R1881.1 U40.8(VCC) U42.5(VCC) U46.16(VCC) U168.5(VCC) ; also on sheet 2 3 5 6 8 9 10 11 12 15 16 17 20 21 22 25 26 27 30 31 33 34 35 37 38 39 45 47 49 50 51 52 54 55 59 60 61 62 63 72 73 74 76 79 83 84 87 88 89 90 91 92 93 94 95 96 97 98 99 159 161 166 168 173 174 176 177 179 180 182 183 184
P5V: D24.K(CATHODE) D25.K(CATHODE) JP5.1 R741.1 R746.1 ; also on sheet 45 59 76 80 82 176
P5V_STBY: JP5.3 R374.1 R386.1 R1156.2 ; also on sheet 4 5 6 8 14 15 19 20 24 25 29 30 33 34 37 38 59 61 76 95
P12V_FAN: F6.1 ; also on sheet 59
P12V_FAN1: C35.2 C36.2 D12.K(CATHODE) F6.2 FANCN1.2 FANCN2.2
PVCCIO: R753.1 R865.1 ; also on sheet 11 16 26 35 39 46 47 87 97 100 101 102 103 120 129 130 139 160 173 177 179 182
BEEP_LED: BPLED1.A R799.2
BIOS_ERR_TRIGGER_N: BPLED1.K Q20.D ; also on sheet 166 177
BMC_HIGH_HEX_0: R713.1 ; also on sheet 180
BMC_HIGH_HEX_1: R718.1 ; also on sheet 180
BMC_HIGH_HEX_2: R720.1 ; also on sheet 180
BMC_HIGH_HEX_3: R725.1 ; also on sheet 180
BMC_LOW_HEX_0: R271.1 ; also on sheet 180
BMC_LOW_HEX_1: R280.1 ; also on sheet 180
BMC_LOW_HEX_2: R407.1 ; also on sheet 180
BMC_LOW_HEX_3: R698.1 ; also on sheet 180
BMC_UART_L_LED: U48.6(D1) ULED1.K
BMC_UART_R_LED: U48.3(D2) ULED2.K
BOARD_ID0: R1132.1 R1134.1 ; also on sheet 177
BOARD_ID0_PCH: R1161.1 R1162.1 ; also on sheet 48
BOARD_ID1: R362.1 R463.1 ; also on sheet 177
BOARD_ID1_PCH: R378.1 R468.1 ; also on sheet 90
BOARD_ID2: R467.1 R478.1 ; also on sheet 177
BOARD_ID2_PCH: R484.1 R494.1 ; also on sheet 48
BOARD_ID3: R366.1 R465.1 ; also on sheet 177
BOARD_ID3_PCH: R370.1 R487.1 ; also on sheet 90
CH_SELECT0: JP14.1 ; also on sheet 52
CH_SELECT1: JP15.1 ; also on sheet 52
CLK_50M_NIC: LAN1.2(NC_SI_CLK_IN) R2159.2 ; also on sheet 55
CLK_100M_NIC_PE_DN: LAN1.25(PECLKN) ; also on sheet 56
CLK_100M_NIC_PE_DP: LAN1.26(PECLKP) ; also on sheet 56
COM1_RXD: U46.10(2B1) ; also on sheet 180
COM1_TXD: U46.6(1B1) ; also on sheet 180
COM2_RXD: R1218.1 U46.11(2B2) ; also on sheet 180
COM2_RXD_HDR: C689.1 CN2.2 R1218.2
COM2_TXD: R1216.1 U46.5(1B2) ; also on sheet 180
COM2_TXD_HDR: C688.1 CN2.1 R1216.2
COM3_RXD: U46.12(2B3) ; also on sheet 93
COM3_TXD: U46.4(1B3) ; also on sheet 93
DB_PRESENT_BMC_N: D4.1 R254.1 ; also on sheet 177
DB_PRESENT_N: D4.2 ; also on sheet 90
FAN0_PWM: R743.1 U168.6(1Y) ; also on sheet 93
FAN0_PWM_BMC: R895.2 U168.1(1A) ; also on sheet 52 177
FAN0_PWM_CN: D24.A(ANODE) FANCN2.4 R741.2 R743.2
FAN0_TACH: D20.K(CATHODE) R742.1 ; also on sheet 93
FAN0_TACH0A: D21.K(CATHODE) R744.1 ; also on sheet 93
FAN0_TACH0A_BMC: D21.A(ANODE) ; also on sheet 177
FAN0_TACH0A_CN: FANCN2.5 R744.2
FAN0_TACH_BMC: D20.A(ANODE) ; also on sheet 177
FAN0_TACH_CN: FANCN2.3 R742.2
FAN1_PWM: R748.1 U168.4(2Y)
FAN1_PWM_BMC: R903.2 U168.3(2A) ; also on sheet 52 177
FAN1_PWM_CN: D25.A(ANODE) FANCN1.4 R746.2 R748.2
FAN1_TACH: D22.K(CATHODE) R747.1 ; also on sheet 93
FAN1_TACH1A: D23.K(CATHODE) R745.1 ; also on sheet 93
FAN1_TACH1A_BMC: D23.A(ANODE) ; also on sheet 177
FAN1_TACH1A_CN: FANCN1.5 R745.2
FAN1_TACH_BMC: D22.A(ANODE) ; also on sheet 177
FAN1_TACH_CN: FANCN1.3 R747.2
FM_PCH_LAN1_DISABLE_N: LAN1.28(DEV_OFF#) R1232.2 ; also on sheet 90 174
HDD_LED_SATA_ACT_N: HDLED1.K ; also on sheet 91
HIGH_HEX_0: DBG1.5 R713.2 ; also on sheet 52
HIGH_HEX_1: DBG1.6 R718.2 ; also on sheet 52
HIGH_HEX_2: DBG1.7 R720.2 ; also on sheet 52
HIGH_HEX_3: DBG1.8 R725.2 ; also on sheet 52
I210_CBOT: C319.2 LAN1.37(CBOT)
I210_CTOP: C319.1 LAN1.40(CTOP)
IRQ_LVC3_WAKE_N: R2166.1 ; also on sheet 74 81 83 88 94 95 168
IRQ_LVC3_WAKE_N_210: LAN1.16(PE_WAKE#) R2166.2
LAN1_51: LAN1.51(VDD3P3) R343.2 R383.2
LAN1_56: LAN1.56(VDD1P5) R344.2
LAN_MAIN_PWR_OK: LAN1.1(LAN_PWR_GOOD) R978.1
LAN_SE_RSET: LAN1.48(RSET) R2129.2
LAN_SMB_ALERT_N: R1015.2 ; also on sheet 74 94 95
LAN_SMB_ALERT_N_I210: LAN1.35(SMB_ALRT#) R1015.1
LAN_SMB_CLK: R1013.2 ; also on sheet 74 77 94 95
LAN_SMB_CLK_I210: LAN1.34(SMB_CLK) R941.2 R1013.1
LAN_SMB_DAT: R1014.2 ; also on sheet 74 77 94 95
LAN_SMB_DAT_I210: LAN1.36(SMB_DAT) R942.2 R1014.1
LED_MDI0_1G_N: LAN1.33(LED2) ; also on sheet 63
LED_MDI0_100M_N: LAN1.31(LED0) ; also on sheet 63
LED_MDI0_LINK_N: LAN1.30(LED1) ; also on sheet 63
LED_PWR_SI_BMC_R_N: PWLED1.A R1156.1
LED_PWRBLINK_BMC: R1868.2 R1881.2 ; also on sheet 74
LED_PWRBLINK_SSB_R: R1868.1 U42.1(B)
LED_PWRSW: PWLED1.K U42.4(Y)
LED_SATA_ACT_R_N: HDLED1.A R1155.2
LOW_HEX_0: DBG1.1 R271.2 ; also on sheet 52
LOW_HEX_1: DBG1.2 R280.2 ; also on sheet 52
LOW_HEX_2: DBG1.3 R407.2 ; also on sheet 52
LOW_HEX_3: DBG1.4 R698.2 ; also on sheet 52
NCSI_ARB_IN: LAN1.43(NC_SI_ARB_IN) TP480.1
NCSI_ARB_OUT: LAN1.44(NC_SI_ARB_OUT) TP479.1
NIC0_MDI0_N0: LAN1.57(MDI_MINUS0) ; also on sheet 63
NIC0_MDI0_N1: LAN1.54(MDI_MINUS1) ; also on sheet 63
NIC0_MDI0_N2: LAN1.52(MDI_MINUS2) ; also on sheet 63
NIC0_MDI0_N3: LAN1.49(MDI_MINUS3) ; also on sheet 63
NIC0_MDI0_P0: LAN1.58(MDI_PLUS0) ; also on sheet 63
NIC0_MDI0_P1: LAN1.55(MDI_PLUS1) ; also on sheet 63
NIC0_MDI0_P2: LAN1.53(MDI_PLUS2) ; also on sheet 63
NIC0_MDI0_P3: LAN1.50(MDI_PLUS3) ; also on sheet 63
NIC1_PCIE_OFF_N: LAN1.61(SDP1/PCIE_DIS) R938.2 ; also on sheet 182
NIC_JTCK: LAN1.19(JTAG_CLK) R949.1 TP475.1
NIC_JTDI: LAN1.29(JTAG_TDI) R950.1 TP477.1
NIC_JTDO: LAN1.4(JTAG_TDO) R951.1 TP478.1
NIC_JTMS: LAN1.18(JTAG_TMS) R953.1 TP476.1
NVM_CS_N: LAN1.15(NVM_CS#) R1011.1
NVM_CS_N_R: R1011.2 U40.1(CS#)
NVM_SI: LAN1.12(NVM_SI) R1010.1
NVM_SI_R: R1005.2 R1009.1 R1010.2 U40.5(DI/IO0)
NVM_SK: LAN1.13(NVM_SK) R1012.1
NVM_SK_R: R1008.1 R1012.2 U40.6(CLK)
NVM_SO: LAN1.14(NVM_SO) R2134.2
NVM_SO_R: R1002.2 R2134.1 U40.2(DO/IO1)
P2E_WBG_LAN_RX_C_DN_5: C318.2 ; also on sheet 92
P2E_WBG_LAN_RX_C_DP_5: C317.2 ; also on sheet 92
P2E_WBG_LAN_RX_DN_5: C318.1 LAN1.20(PE_TN)
P2E_WBG_LAN_RX_DP_5: C317.1 LAN1.21(PE_TP)
P2E_WBG_LAN_TX_C_DN_5: LAN1.23(PE_RN) ; also on sheet 92
P2E_WBG_LAN_TX_C_DP_5: LAN1.24(PE_RP) ; also on sheet 92
PECI_BMC: R753.2 R754.1 ; also on sheet 177
PECI_CPU_G: R754.2 R755.2 ; also on sheet 129 139
PECI_PCH: R755.1 R865.2 ; also on sheet 91
PH_CH0: JP14.3 R372.2
PH_CH1: JP15.3 R381.2
PWRGD_PS_PWROK: U42.2(A) ; also on sheet 51 59
REVISION_ID0: R1159.1 R1160.1 ; also on sheet 177
REVISION_ID0_PCH: R1165.1 R1166.1 ; also on sheet 90
REVISION_ID1: R1136.1 R1140.1 ; also on sheet 177
REVISION_ID1_PCH: R1163.1 R1167.1 ; also on sheet 90
REVISION_ID2: R1157.1 R1158.1 ; also on sheet 177
REVISION_ID2_PCH: R1169.1 R1170.1 ; also on sheet 90
REVISION_ID3: R1138.1 R1141.1 ; also on sheet 177
REVISION_ID3_PCH: R1164.1 R1168.1 ; also on sheet 48
RMII_BMC_CRS_DV: LAN1.3(NC_SI_CRS_DV) R2158.2 ; also on sheet 180
RMII_BMC_PHY_TXD0: LAN1.9(NC_SI_TXD0) R894.2 ; also on sheet 180
RMII_BMC_PHY_TXD1: LAN1.8(NC_SI_TXD1) R902.2 ; also on sheet 180
RMII_BMC_TX_EN: LAN1.7(NC_SI_TX_EN) R2157.2 ; also on sheet 180
RMII_PHY_BMC_RXD0: LAN1.6(NC_SI_RXD0) R904.2 ; also on sheet 180
RMII_PHY_BMC_RXD1: LAN1.5(NC_SI_RXD1) R906.2 ; also on sheet 180
RST_DBG_RSTBTN_N: DBG1.11 ; also on sheet 168
RST_PCIE_PCH_DEV_N: R2165.1 ; also on sheet 51 74 83
RST_PERST1_N_210: LAN1.17(PE_RST#) R907.1 R2165.2
SERIAL_RXD: DBG1.10 R263.2
SERIAL_RXD_R: R263.1 U46.9(2A)
SERIAL_TXD: DBG1.9 R262.2
SERIAL_TXD_R: R262.1 U46.7(1A)
SPEAKER_PCH: Q20.G ; also on sheet 90 174
SWITCH_EA_N: R1201.1 U46.15(2OE#)
SWITCH_EB_N: R1200.1 U46.1(1OE#)
SWITCH_S0: JP14.2 R1204.1 U46.14(S0) U48.5(G2) ; also on sheet 180
SWITCH_S1: JP15.2 R1202.1 U46.2(S1) U48.2(G1) ; also on sheet 180
TP_SDP0: LAN1.63(SDP0) TP474.1
TP_SDP2: LAN1.62(SDP2) TP472.1
TP_SDP3: LAN1.60(SDP3) TP471.1
U27_HOLD_N: R1004.2 U40.7(HOLD#/IO3)
U27_WP_N: R982.2 U40.3(WP#/IO2)
UART_LED_L: R806.2 ULED1.A
UART_LED_R: R807.2 ULED2.A
UART_PWR_SEL: C854.1 DBG1.14 JP5.2
UART_SELECT: Q23.D R387.2 ; also on sheet 52 180
UART_SELECT_D1_N: D27.K D28.A
UART_SELECT_D2_N: D28.K D29.A
UART_SELECT_D3_N: D29.K Q6.B
UART_SELECT_D3_Q_N: D4.3 Q7.D R385.2
UART_SELECT_D3_R_N: Q6.C Q7.G R409.2
UART_SELECT_N: D27.A DBG1.12 Q4.E R374.2
UART_SELECT_Q4: Q4.B R384.1 R386.2
UART_SELECT_Q4_N: Q4.C Q23.G R391.2
XTAL_IN_I210: LAN1.46(XTAL1) R2126.2
XTAL_IN_I210_R: C7280.2 R2126.1 X6.2
XTAL_OUT_I210: LAN1.45(XTAL2) R2127.2
XTAL_OUT_I210_R: C7282.2 R2127.1 X6.1

Not connected (* = marked no-connect by the designer): FANCN1 6* NP1*; FANCN2 6* NP1*; LAN1 22(NC#22)*; U46 3(1B4)* 13(2B4)*

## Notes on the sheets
sheet 64
- FAB2 REV001 20150701
- INTEL I210
- NOPOP I210
- FAB1 REV014 20150416
- From PCH PCIe port 5
- From CLK buffer
- Synchronous clock
- From CPLD
- 50MHz +/- 100ppm
- Layout Note:
  1) Place close to chip.
  2) Chip to RES should be less than 500 mils.
- From BMC
- To BMC
- From PCH PCIe port 5
- Layout Note:
  1) Place CAPs close to Xtal.
  2) Total trace lengths from chip to Xtal
     should be less than 750 mils.
  3) These traces are NOT differential signals.
- FAB1 REV014 20150415
- Loading capacitance (CL) : 12.0pF ∮ 0.2 pF
- ∮30ppm at 25deg.C∮  3deg.C
- 4.99K 1% Place near chip
- Pin 47: 1.5V power supply to the crystal oscillator and
  bandgap.
  Pin 56: In BASE-T, 1.5V analog power supply to GPHY; in
  SerDes, not connected.
- Pin 51: In BASE-T, 3.3V analog power supply to GPHY; in
  SerDes, 1.5V analog power supply to SGMII SerDes.
- Place this cap. close to chip.
- FAB1 REV012 20150409
- Layout Note : Keep SPI traces short
- There should be at least 100 ms between the
  time that LAN_PWR_GOOD(1) goes high until
  PE_RST_N(17) goes high.
- 8Mb flash
- The 33 K pull-down resistor can be left
  unstuffed in case the platform does not
  require enabling JTAG interface.
sheet 65
- HDD LED
- Vf = 2.0V
- If = 20mA
- Please place close to SATA0
- FAB1 REV011 20150408
- FAB1 REV005 20150323
- YELLOW LED
- GREEN LED
- Vf = 2.0V
- BEEP LED
- 83.01221.Q70
- 83.01221.N70
- If = 20mA
- FAB1 REV014 20150416
- Power LED and System Identification LED
- Change to 84.27002.N31
- Please place close to PWRON1
- Vf = 2.0V
- If = 20mA
- BLUE LED
- Vf = 3.5V
- If = 20mA
- FAB1 REV013 20150413
- GREEN LED
- Power off, Chassis identify off:  LED consistently off
  Power off, Chassis identify on:   LED on for 0.1sec, off for 0.9sec, and loop
  Power on, Chassis identify off:   LED consistently on
  Power on, Chassis identify on:    LED on for 0.9sec, off for 0.1sec, and loop
- Change to 75.04001.07C
- 83.00270.B70
- FAB1 REV005 20150322
- FAB1 REV003 20150318
- Vf = 2.0V
- If = 20mA
- GREEN LED
- 83.00270.B70
- FAB1 20150312
- From BMC
- INPUT
- OUTPUT
- A
- B
- Y
- L
- L
- L
- L
- H
- H
- H
- L
- H
- H
- H
- L
sheet 66
- FAN - PWM
- Layout Note:
  Place near fan connector.
- FAB1 20150305
- FAB1 REV004 20150320
- FAN - CONNECTOR
- This should be placed
  as close as possible
  to FANCN1
  ZENER Voltage :14V
- FAB1 REV005 20150322
- FAB1 REV011 20150407
- Vf = 0.29 - 0.37V
- This should be placed
  as close as possible
  to FANCN1
  ZENER Voltage :14V
- Vf = 0.29 - 0.37V
sheet 68
- PECI
- PECI
- CAD NOTE:
  STUFF PULL-UP R865 IF BMC PECI IS NOT USED
  UNSTUFF PULL-UP R753 IF PCH PECI IS USED
- CAD NOTE:
  R754 STUFFED WHEN BMC IS PECI'S MASTER
  EMPTY FOR DCMI SKU OR NM DEBUG
- CAD Note:
  AS CLOSE AS POSSIBLE TO THE COMMON NODE
  PLACE ALL 3 STUFFING OPTION RESISTORS
  SO THAT THE PECI BUS STUB IS AS SHORT AS
  POSSIBLE WHEN ANY OF THEM IS UNSTUFFED
- PDG P.598
sheet 69
- DEBUG PORT
- UART connection change among host console (Default)
- --> BMC debug console --> midplane console and loop.
- 1-2 (Default)
- FAB1 REV005 20150322
- FAB2 REV001 20150708
- Change to ASP-165694-02
- FAB1 REV007 20150325
- If debug card not plugged, Vmax to conduct D27 - D29 and Q6 is 1V*3+0.85V = 3.85V
- If debug card not plugged, Vmin to conduct D27 - D29 and Q6 is 0.62V*3+0.65V = 2.51V
- If debug card is plugged, V = 5*10K/(15K+10K) = 2V, Q4 off and Q6 off.
- If select button is pressed, V = 0V, Q4 on and Q6 off.
- FAB1 REV014 20150416
- Change to 84.27002.N31
- Vf,max = 1V
- Vf,max = 1V
- Vf,max = 1V
- Vbe,max = 0.85V
- Vf,min = 0.62V
- Vf,min = 0.62V
- Vf,min = 0.62V
- Vbe,min = 0.65V
- V = 5 * (10K/25K) = 2V
- FAB1 REV014 20150416
- Change to 84.27002.N31
- Debug card has 10K pull down for pin12, with a white UART channel
  selection button between Pin12 and ground.
sheet 70
- COM PORT SELECTION
- FAB1 REV005 20150322
- INPUTS
- SELECT
- INPUT/OUTPUT
- Function
- OE
- S1
- S0
- A
- L
- L
- L
- B1
- A port = B1 port
- L
- L
- H
- B2
- A port = B2 port
- L
- H
- L
- B3
- A port = B3 port
- L
- H
- H
- B4
- A port = B4 port
- FAB2 REV001 20150707
- H
- X
- X
- Z
- Disconnet
- FAB1 REV007 20150325
- 1-2(Default)
- Normal
- BMC CONSOLE
- ONLY FOR BMC DEBUGGING
sheet 71
- AST1250 ID SETTING
- BOARD ID
- EVT 20150206
- BOARD_ID
- VERSION
- ID3
- ID2
- ID1
- ID0
- RESERVED
- 0
- 0
- 0
- 0
- Leopard /Orv1/mSATA
- 0
- 0
- 0
- 1
- RESERVED
- 0
- 0
- 1
- 0
- RESERVED
- 0
- 0
- 1
- 1
- RESERVED
- 0
- 1
- 0
- 0
- Cubby Orv2 /mSATA
- 0
- 1
- 0
- 1
- Leopard /Orv1/M.2
- 0
- 1
- 1
- 0
- Cubby Orv2 /M.2
- 0
- 1
- 1
- 1
- FAB REVISION ID
- FAB4 REV001 20160314
- REVISION_ID
- ID3
- ID2
- ID1
- ID0
- FAB1
- 0
- 0
- 0
- 0
- FAB2
- 0
- 0
- 0
- 1
- FAB3
- 0
- 0
- 1
- 0
- FAB4
- 0
- 0
- 1
- 1
- 0
- 1
- 0
- 0
